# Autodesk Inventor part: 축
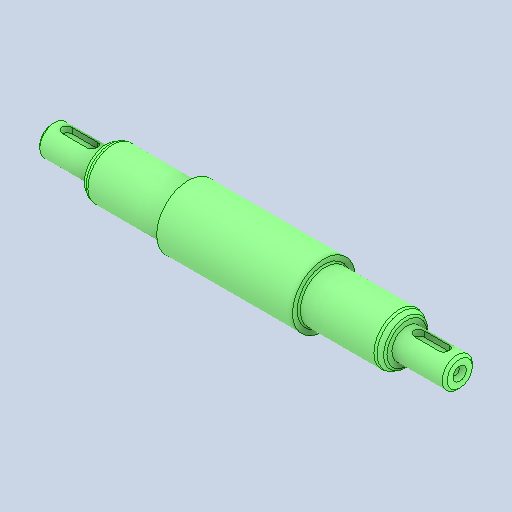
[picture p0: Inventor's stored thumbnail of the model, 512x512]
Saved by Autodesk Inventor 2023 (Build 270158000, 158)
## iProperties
Created: 2026-03
Part Number: 축
Material: 강철, 탄소
Document SubType Name: Modeling
Designer: 4강의실
Density: 7.85 g/cm^3
Appearance: 기본값
Author: jhkim
Sending System: Autodesk Inventor 2026
Preprocessor: ST-DEVELOPER v20.1
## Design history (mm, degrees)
feature "솔리드1"
node "솔리드2"
